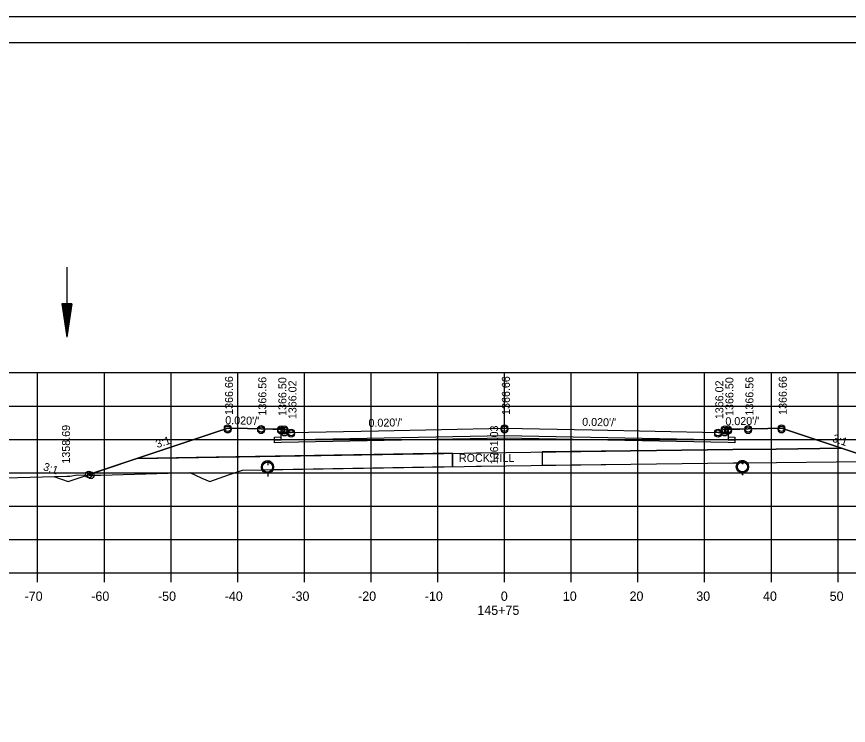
# Model space of a CAD drawing. Extents: x 1374311 to 1383814, y 384102 to 406278.
# Drawn here: x 1381555.5 to 1381680.2, y 390618.5 to 390724.7 of the extents above; entities that cross this region are included whole.
import ezdxf

# ---------------------------------------------------------------- set-up
doc = ezdxf.new("R2010")
doc.units = 0
for name, color, linetype in [('R_Axis', 7, 'Continuous'), ('R_Axis Annot', 7, 'Continuous'), ('R_Border', 7, 'Continuous'), ('R_Draft', 7, 'Continuous'), ('R_Exist Surface', 7, 'Continuous'), ('R_Fin Surface', 7, 'Continuous'), ('R_Grid', 7, 'Continuous'), ('R_No Plot', 7, 'Continuous'), ('R_Water', 7, 'Continuous'), ('R_Xsect Elev', 7, 'Continuous'), ('R_Xsect Slope', 7, 'Continuous')]:
    doc.layers.add(name, color=color, linetype=linetype)

msp = doc.modelspace()

# ---------------------------------------------------------------- linework, layer by layer
at = {"layer": 'R_Axis'}
for p, q in [((1381488.66, 390641.38), (1381768.66, 390641.38)), ((1381558.66, 390639.98), (1381558.66, 390641.38)), ((1381568.66, 390639.98), (1381568.66, 390641.38)), ((1381578.66, 390639.98), (1381578.66, 390641.38)), ((1381588.66, 390639.98), (1381588.66, 390641.38)), ((1381598.66, 390639.98), (1381598.66, 390641.38)), ((1381608.66, 390639.98), (1381608.66, 390641.38)), ((1381618.66, 390639.98), (1381618.66, 390641.38)), ((1381628.66, 390639.98), (1381628.66, 390641.38)), ((1381638.66, 390639.98), (1381638.66, 390641.38)), ((1381648.66, 390639.98), (1381648.66, 390641.38)), ((1381658.66, 390639.98), (1381658.66, 390641.38)), ((1381668.66, 390639.98), (1381668.66, 390641.38)), ((1381678.66, 390639.98), (1381678.66, 390641.38))]:
    msp.add_line(p, q, dxfattribs=at)
at = {"layer": 'R_Border'}
for p, q in [((1381470.66, 390720.84), (1381786.84, 390720.84)), ((1381623.18, 390720.58), (1381623.18, 390720.58)), ((1381623.18, 390720.58), (1381623.18, 390720.58))]:
    msp.add_line(p, q, dxfattribs=at)
at = {"layer": 'R_Draft'}
for p, q in [((1381562.31, 390681.68), (1381563.06, 390676.68)), ((1381563.81, 390681.68), (1381562.31, 390681.68)), ((1381562.43, 390681.68), (1381563.06, 390677.51)), ((1381562.56, 390681.68), (1381563.06, 390678.37)), ((1381562.68, 390681.68), (1381563.06, 390679.21)), ((1381562.81, 390681.68), (1381563.06, 390680.05)), ((1381562.94, 390681.68), (1381563.06, 390680.89)), ((1381563.81, 390681.68), (1381563.06, 390676.68)), ((1381563.3, 390681.68), (1381563.06, 390680.05)), ((1381563.55, 390681.68), (1381563.06, 390678.37)), ((1381563.68, 390681.68), (1381563.06, 390677.51)), ((1381563.43, 390681.68), (1381563.06, 390679.21)), ((1381563.17, 390681.68), (1381563.06, 390680.89))]:
    msp.add_line(p, q, dxfattribs=at)
at = {"layer": 'R_Exist Surface'}
for p, q in [((1381593.15, 390658.18), (1381593.15, 390657.66)), ((1381664.24, 390658.05), (1381664.45, 390657.9)), ((1381593.15, 390656.35), (1381593.15, 390655.83)), ((1381664.24, 390656.21), (1381664.45, 390656.06))]:
    msp.add_line(p, q, dxfattribs=at)
msp.add_lwpolyline([(1381552.01, 390655.57), (1381563.05, 390655.85), (1381563.48, 390655.89), (1381564.64, 390656.07), (1381568.13, 390656.02), (1381578.24, 390656.34), (1381581.5, 390656.43), (1381583.26, 390655.59), (1381584.48, 390655.08), (1381587.25, 390656.05), (1381589.39, 390656.79), (1381622.62, 390657.33), (1381624.38, 390657.36), (1381624.7, 390657.36), (1381625.01, 390657.37), (1381625.16, 390657.37), (1381647.58, 390657.67), (1381651.45, 390657.7), (1381662.92, 390657.86), (1381669.41, 390657.91), (1381678.38, 390658.03), (1381687.74, 390658.1)], dxfattribs=at)
for centre in [(1381593.12, 390657.23), (1381664.32, 390657.27)]:
    msp.add_circle(centre, 0.917, dxfattribs=at)
at = {"layer": 'R_Fin Surface'}
for p, q in [((1381573.59, 390658.53), (1381566.35, 390656.12)), ((1381620.86, 390659.3), (1381573.59, 390658.53)), ((1381620.86, 390659.3), (1381620.86, 390657.3)), ((1381620.86, 390657.3), (1381620.86, 390659.3)), ((1381634.3, 390659.49), (1381634.3, 390657.49)), ((1381634.3, 390659.49), (1381634.3, 390657.49)), ((1381593.96, 390656.86), (1381620.86, 390657.3)), ((1381651.45, 390657.7), (1381662.92, 390657.86)), ((1381662.92, 390657.86), (1381663.62, 390657.87)), ((1381578.24, 390656.34), (1381581.5, 390656.43)), ((1381584.48, 390655.08), (1381587.25, 390656.05)), ((1381587.25, 390656.05), (1381589.39, 390656.79)), ((1381589.39, 390656.79), (1381592.3, 390656.83))]:
    msp.add_line(p, q, dxfattribs=at)
for points in [[(1381561.08, 390655.8), (1381563.24, 390655.08), (1381578.92, 390660.31), (1381587.15, 390663.05), (1381590.1, 390662.99), (1381592.15, 390662.95), (1381593.92, 390662.91), (1381595.15, 390662.89), (1381595.35, 390662.89), (1381595.65, 390662.89), (1381595.65, 390662.59), (1381595.66, 390662.39), (1381596.07, 390662.4), (1381596.66, 390662.41), (1381609.78, 390662.67), (1381628.66, 390663.05), (1381641.78, 390662.79), (1381660.66, 390662.41), (1381661.07, 390662.4), (1381661.66, 390662.39), (1381661.66, 390662.68), (1381661.67, 390662.89), (1381661.87, 390662.89), (1381662.17, 390662.89), (1381663.94, 390662.92), (1381665.17, 390662.95), (1381668.12, 390663.01), (1381670.17, 390663.05), (1381678.88, 390660.14), (1381684.97, 390658.12)], [(1381662.17, 390662.53), (1381662.18, 390661.38), (1381663.18, 390661.37), (1381663.17, 390660.87), (1381662.17, 390660.89), (1381628.66, 390661.56), (1381595.15, 390660.89), (1381594.15, 390660.87), (1381594.16, 390661.37), (1381595.16, 390661.38), (1381595.15, 390662.53)], [(1381573.59, 390658.53), (1381622.59, 390659.33), (1381624.35, 390659.36), (1381624.68, 390659.36), (1381624.99, 390659.37), (1381625.13, 390659.37), (1381647.56, 390659.67), (1381651.43, 390659.7), (1381662.9, 390659.86), (1381669.39, 390659.91), (1381679.19, 390660.04)], [(1381679.19, 390660.04), (1381669.39, 390659.91), (1381662.9, 390659.86), (1381651.43, 390659.7), (1381647.56, 390659.67), (1381634.3, 390659.49)], [(1381665.01, 390657.88), (1381669.41, 390657.91), (1381678.38, 390658.03), (1381684.97, 390658.08), (1381684.97, 390658.12), (1381679.19, 390660.04)], [(1381634.3, 390657.49), (1381647.58, 390657.67), (1381651.45, 390657.7)], [(1381566.35, 390656.12), (1381566.35, 390656.04), (1381568.13, 390656.02), (1381578.24, 390656.34)], [(1381581.5, 390656.43), (1381583.26, 390655.59), (1381584.48, 390655.08)]]:
    msp.add_lwpolyline(points, dxfattribs=at)
for centre, start, end in [((1381593.12, 390657.23), 336.3483, 205.5155), ((1381664.32, 390657.27), 41.3632, 139.5928)]:
    msp.add_arc(centre, 0.917, start, end, dxfattribs=at)
at = {"layer": 'R_Grid'}
for p, q in [((1381488.66, 390671.38), (1381768.66, 390671.38)), ((1381558.66, 390641.38), (1381558.66, 390671.38)), ((1381568.66, 390641.38), (1381568.66, 390671.38)), ((1381578.66, 390641.38), (1381578.66, 390671.38)), ((1381588.66, 390641.38), (1381588.66, 390671.38)), ((1381598.66, 390641.38), (1381598.66, 390671.38)), ((1381608.66, 390641.38), (1381608.66, 390671.38)), ((1381618.66, 390641.38), (1381618.66, 390671.38)), ((1381628.66, 390641.38), (1381628.66, 390671.38)), ((1381638.66, 390641.38), (1381638.66, 390671.38)), ((1381648.66, 390641.38), (1381648.66, 390671.38)), ((1381658.66, 390641.38), (1381658.66, 390671.38)), ((1381668.66, 390641.38), (1381668.66, 390671.38)), ((1381678.66, 390641.38), (1381678.66, 390671.38)), ((1381488.66, 390666.38), (1381768.66, 390666.38)), ((1381488.66, 390661.38), (1381768.66, 390661.38)), ((1381488.66, 390656.38), (1381768.66, 390656.38)), ((1381488.66, 390651.38), (1381768.66, 390651.38)), ((1381488.66, 390646.38), (1381768.66, 390646.38)), ((1381488.66, 390641.38), (1381768.66, 390641.38))]:
    msp.add_line(p, q, dxfattribs=at)
at = {"layer": 'R_No Plot'}
msp.add_line((1381458.26, 390724.74), (1381791.59, 390724.74), dxfattribs=at)
for points in [[(1381458.25, 390724.74), (1381791.59, 390724.74), (1381791.59, 390511.4), (1381458.25, 390511.4)], [(1381704.58, 390720.84), (1381704.58, 390710.96), (1381740.31, 390710.96), (1381740.31, 390708.04), (1381763.51, 390708.04), (1381763.51, 390684.83), (1381786.84, 390684.83), (1381786.84, 390515.38), (1381470.66, 390515.38), (1381470.66, 390720.84)]]:
    msp.add_lwpolyline(points, close=True, dxfattribs=at)
msp.add_lwpolyline([(1381684.97, 390658.12), (1381678.88, 390660.14), (1381670.17, 390663.05), (1381668.12, 390663.01), (1381665.17, 390662.95), (1381663.94, 390662.92), (1381662.17, 390662.89), (1381662.18, 390661.74), (1381663.18, 390661.73), (1381663.17, 390661.23), (1381662.17, 390661.25), (1381628.66, 390661.92), (1381595.15, 390661.25), (1381594.15, 390661.23), (1381594.16, 390661.73), (1381595.16, 390661.74), (1381595.15, 390662.89), (1381593.92, 390662.91), (1381592.15, 390662.95), (1381590.1, 390662.99), (1381587.15, 390663.05), (1381578.92, 390660.31), (1381566.35, 390656.12), (1381566.35, 390656.04), (1381568.13, 390656.02), (1381578.24, 390656.34), (1381581.5, 390656.43), (1381583.26, 390655.59), (1381584.48, 390655.08), (1381587.25, 390656.05), (1381589.39, 390656.79), (1381622.62, 390657.33), (1381624.38, 390657.36), (1381624.7, 390657.36), (1381625.01, 390657.37), (1381625.16, 390657.37), (1381647.58, 390657.67), (1381651.45, 390657.7), (1381662.92, 390657.86), (1381669.41, 390657.91), (1381678.38, 390658.03), (1381684.97, 390658.08)], dxfattribs=at)
for centre in [(1381587.15, 390663.05), (1381587.15, 390663.05), (1381592.15, 390662.95), (1381592.15, 390662.95), (1381595.15, 390662.89), (1381595.15, 390662.89), (1381595.65, 390662.89), (1381595.65, 390662.89), (1381628.66, 390663.05), (1381628.66, 390663.05), (1381661.67, 390662.89), (1381661.67, 390662.89), (1381662.17, 390662.89), (1381662.17, 390662.89), (1381665.17, 390662.95), (1381665.17, 390662.95), (1381670.17, 390663.05), (1381670.17, 390663.05), (1381587.15, 390662.84), (1381592.15, 390662.74), (1381595.15, 390662.68), (1381595.65, 390662.68), (1381595.66, 390662.39), (1381596.66, 390662.41), (1381596.66, 390662.41), (1381596.66, 390662.2), (1381628.66, 390662.84), (1381660.66, 390662.41), (1381660.66, 390662.41), (1381660.66, 390662.2), (1381661.66, 390662.39), (1381661.67, 390662.68), (1381662.17, 390662.68), (1381665.17, 390662.74), (1381670.17, 390662.84), (1381566.35, 390656.12), (1381566.35, 390656.12), (1381566.35, 390656.12), (1381566.35, 390656.12), (1381566.63, 390656), (1381566.63, 390656)]:
    msp.add_circle(centre, 0.5, dxfattribs=at)
at = {"layer": 'R_Water'}
for p, q in [((1381563.06, 390687.18), (1381563.06, 390676.68)), ((1381593.15, 390658.02), (1381593.15, 390657.49)), ((1381664.24, 390657.88), (1381664.45, 390657.73)), ((1381593.15, 390656.52), (1381593.15, 390655.99)), ((1381664.24, 390656.38), (1381664.45, 390656.23))]:
    msp.add_line(p, q, dxfattribs=at)
for centre in [(1381593.12, 390657.23), (1381664.32, 390657.27)]:
    msp.add_circle(centre, 0.75, dxfattribs=at)

# ---------------------------------------------------------------- texts
at = {"layer": 'R_Axis Annot'}
for s, p in [('-70', (1381556.7, 390637.18)), ('-60', (1381566.7, 390637.18)), ('-50', (1381576.7, 390637.18)), ('-40', (1381586.7, 390637.18)), ('-30', (1381596.7, 390637.18)), ('-20', (1381606.7, 390637.18)), ('-10', (1381616.7, 390637.18)), ('0', (1381628.1, 390637.18)), ('10', (1381637.4, 390637.18)), ('20', (1381647.4, 390637.18)), ('30', (1381657.4, 390637.18)), ('40', (1381667.4, 390637.18)), ('50', (1381677.4, 390637.18)), ('145+75', (1381624.58, 390635.08))]:
    msp.add_text(s, height=1.4, dxfattribs=at).set_placement(p)
at = {"layer": 'R_Fin Surface'}
msp.add_text('ROCK FILL', height=1.2, dxfattribs=at).set_placement((1381621.82, 390658))
at = {"layer": 'R_Xsect Elev'}
for s, p in [('1366.66', (1381587.95, 390665.05)), ('1366.56', (1381592.95, 390664.95)), ('1366.50', (1381595.95, 390664.89)), ('1366.02', (1381597.46, 390664.41)), ('1366.66', (1381629.46, 390665.05)), ('1366.02', (1381661.46, 390664.41)), ('1366.50', (1381662.97, 390664.89)), ('1366.56', (1381665.97, 390664.95)), ('1366.66', (1381670.97, 390665.05)), ('1358.69', (1381563.51, 390657.75)), ('1361.03', (1381627.7, 390657.66))]:
    msp.add_text(s, height=1.2, rotation=90, dxfattribs=at).set_placement(p)
at = {"layer": 'R_Xsect Slope'}
for s, rotation, p in [("0.020'/'", 358.8542, (1381586.78, 390663.66)), ("0.020'/'", 358.8542, (1381640.29, 390663.42)), ("0.020'/'", 1.1458, (1381661.78, 390663.48)), ("0.020'/'", 1.1458, (1381608.27, 390663.24)), ('3:1', 341.5651, (1381677.72, 390661.06)), ('3:1', 18.4349, (1381576.59, 390660.06)), ('3:1', 341.5651, (1381559.39, 390656.8))]:
    msp.add_text(s, height=1.2, rotation=rotation, dxfattribs=at).set_placement(p)

doc.saveas('drawing.dxf')
